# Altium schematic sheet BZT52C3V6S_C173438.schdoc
size 127 x 101 mm
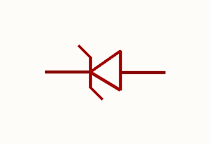
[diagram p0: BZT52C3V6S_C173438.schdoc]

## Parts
D?  bzt52c3v6s_c173438  [SOD-323_L1.8-W1.3-LS2.5-RD]  (value not drawn)

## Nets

Not connected (* = marked no-connect by the designer): D? 1 2

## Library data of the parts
D? = bzt52c3v6s_c173438: 二极管配置:1个独立式;稳压值(标称值):3.6V;稳压值(范围值):3.4V~3.8V;耗散功率(Pd):200mW;; Manufacturer: MDD(辰达半导体); AddInBom: yes; ModelId: db63db13d9e342eb939127d413d6200b; ModelTransform: 104.3305,51.181,0,0,0,0,0,-0.004,0; Diode Configuration: 1个独立式; Zener Voltage(Nom): 3.6V; Reverse Leakage Current (Ir): 10uA; Pd - Power Dissipation: 200mW; Impedance(Zzt): 130Ω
